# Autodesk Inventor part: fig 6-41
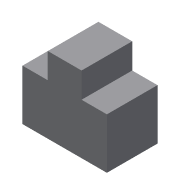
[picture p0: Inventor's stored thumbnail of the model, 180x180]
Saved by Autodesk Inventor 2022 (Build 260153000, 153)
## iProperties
Created: 2005-12
Part Number: fig 6-41
Document SubType Name: Modeling
Designer: CADCIM
Density: 1 g/cm^3
Material: Generic
Appearance: Default
Author: CADCIM
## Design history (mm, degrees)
sketch "Sketch1"
  geometry: L1 (10, 15)-(25, 15); L2 (25, 15)-(25, -15); L3 (25, -15)-(-25, -15); L4 (-25, -15)-(-25, 15); L5 (-25, 15)-(-10, 15); L6 (10, 15)-(10, 30); L7 (10, 30)-(-10, 30); L8 (-10, 30)-(-10, 15)
  constraints: 16 end point, 3 parallel, 3 perpendicular, 2 equal length, 1 collinear, 1 horizontal
  dimensions: "d0" = 50 distance of L2.end L3.end; "d2" = 30 distance of L1.end L2.end; "d3" = 15 distance of L1.start L1.end; "d11" = 15 distance of L7.end L5.end
extrude "Extrusion1" new body sketch "Sketch1" stored distance "d7" = 30; taper "d8" = 0 deg
body "Solid1"
